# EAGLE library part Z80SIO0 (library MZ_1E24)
Z80 FAMILY DEVICE
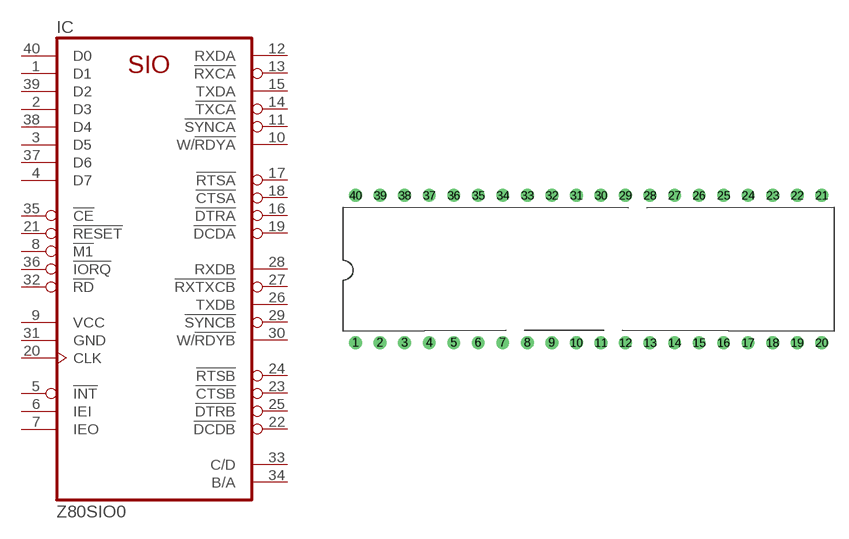
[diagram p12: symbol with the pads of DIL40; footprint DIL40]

Designator prefix IC

## Z80SIO0  [DIL40]
1  D1
2  D3
3  D5
4  D7
5  !INT  out
6  IEI  in
7  IEO  out
8  !M1  in
9  VCC  pwr
10  W/!RDYA  out
11  !SYNCA
12  RXDA  in
13  !RXCA  in
14  !TXCA  in
15  TXDA  out
16  !DTRA  out
17  !RTSA  out
18  !CTSA  in
19  !DCDA  in
20  CLK  in
21  !RESET  in
22  !DCDB  in
23  !CTSB  in
24  !RTSB  out
25  !DTRB  out
26  TXDB  out
27  !RXTXCB  in
28  RXDB  in
29  !SYNCB
30  W/!RDYB  out
31  GND  pwr
32  !RD  in
33  C/D  in
34  B/A  in
35  !CE  in
36  !IORQ  in
37  D6
38  D4
39  D2
40  D0

## Footprint DIL40 (pad centres in mm)
Dual In Line Package
drill 0.813 round: 1 -24.13,-7.62; 2 -21.59,-7.62; 3 -19.05,-7.62; 4 -16.51,-7.62; 5 -13.97,-7.62; 6 -11.43,-7.62; 7 -8.89,-7.62; 8 -6.35,-7.62; 9 -3.81,-7.62; 10 -1.27,-7.62; 11 1.27,-7.62; 12 3.81,-7.62; 13 6.35,-7.62; 14 8.89,-7.62; 15 11.43,-7.62; 16 13.97,-7.62; 17 16.51,-7.62; 18 19.05,-7.62; 19 21.59,-7.62; 20 24.13,-7.62; 21 24.13,7.62; 22 21.59,7.62; 23 19.05,7.62; 24 16.51,7.62; 25 13.97,7.62; 26 11.43,7.62; 27 8.89,7.62; 28 6.35,7.62; 29 3.81,7.62; 30 1.27,7.62; 31 -1.27,7.62; 32 -3.81,7.62; 33 -6.35,7.62; 34 -8.89,7.62; 35 -11.43,7.62; 36 -13.97,7.62; 37 -16.51,7.62; 38 -19.05,7.62; 39 -21.59,7.62; 40 -24.13,7.62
